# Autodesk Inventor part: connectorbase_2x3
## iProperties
Created: 2006-03
Part Number: connectorbase_2x3
Document SubType Name: Modeling
Designer: Elise Moss
Author: Elise Moss
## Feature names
1. Base1
